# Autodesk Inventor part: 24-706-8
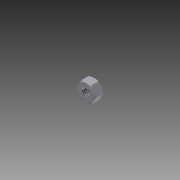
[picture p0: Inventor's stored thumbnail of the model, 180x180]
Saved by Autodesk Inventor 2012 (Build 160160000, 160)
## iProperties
Created: 2004-11
Part Number: 24-706-8
Material: Stainless Steel, Austenitic
Document SubType Name: Modeling
Designer: Autodesk, Inc.
Manufacturer: Standard
Standards Organization: Custom
Description: Hexagon Nut, M8
Catalog Web Link: http://www.parker.com/ead/cm1.asp?cmid=809
Vendor: PARKER IPS
Mass: 6.05208 g
Surface Area: 6.5618 cm^2
Volume: 0.753683 cm^3
Density: 8.03 g/cm^3
CAGE: 1LJX3
Dept. ID: Product Design
Description #2: ---
Finish #1: ---
Finish #2: ---
Material ID: ---
Project Number: ---
Author: Autodesk, Inc.
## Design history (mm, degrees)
sketch "Sketch1"
  geometry: L1 (3.753, -6.5)-(-3.753, -6.5); L2 (-3.753, -6.5)-(-7.506, 0); L3 (-7.506, 0)-(-3.753, 6.5); L4 (-3.753, 6.5)-(3.753, 6.5); L5 (3.753, 6.5)-(7.506, 0); L6 (7.506, 0)-(3.753, -6.5); 1 further point
  constraints: 12 end point, 1 horizontal, 12 other
  dimensions: "Width" = 13 distance between parallel lines of L1 L4
extrude "Extrusion1" new body sketch "Sketch1" taper "d2" = 0 deg; stored distance "Height" = 6.8
sketch "Sketch2"
  geometry: L1 (-7.506, 3.4)-(-7.506, -3.4) reference; L2 (-3.753, -3.4)-(-7.506, -3.4) reference; L3 (-7.506, -2.72)-(-6.5, -3.4); L4 (1.501, 0)-(-9.007, 0) reference; L5 (0, -4.76)-(0, 4.76) reference; 1 further point
  constraints: 2 end point, 2 point on line
  dimensions: "d3" = 13 diameter of L3.end L5 (= Width); "d4" = 5.44 diameter of L3.start L4 (= 0.8 x Height)
revolve "Revolution1" sketch "Sketch2" stored, may be unused: angle "d5" = 90 deg
mirror "Mirror1"
sketch "Sketch3"
  geometry: 1 further point
hole "Hole1" sketch "Sketch3" at (0, 0) diameter "Hole_Dia" = 6.647; stored, may be unused: countersink angle "d10" = 90 deg, drill point angle "d12" = 118 deg; dims "d7" = 6, "d8" = 4, "d9" = 2, "d11" = 8
body "Solid1"
